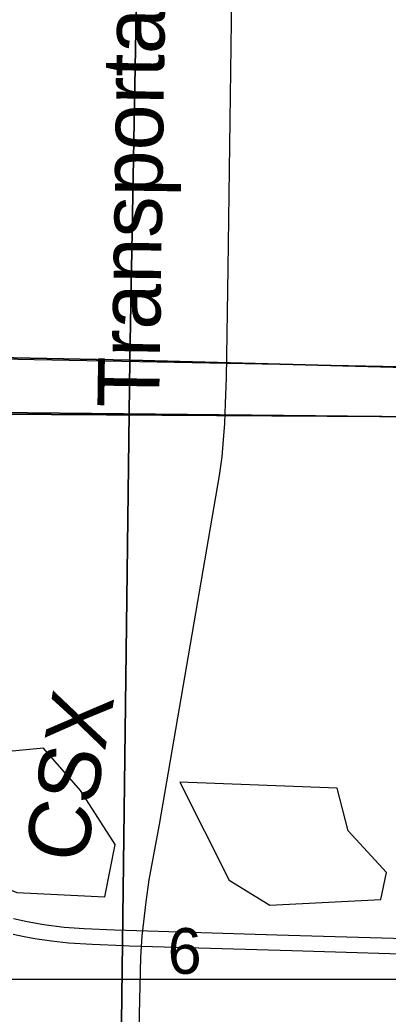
# Model space of a CAD drawing. Extents: x 0 to 68, y 0 to 52.9.
# Drawn here: x 44.214 to 44.57, y 34.705 to 35.667 of the extents above; entities that cross this region are included whole.
import ezdxf

# ---------------------------------------------------------------- set-up
doc = ezdxf.new("R2010")
doc.units = 0
for name, color, linetype in [('Default', 7, 'Continuous'), ('GM_X_Minor_Lake', 7, 'Continuous'), ('GM_X_State_Route', 7, 'Continuous'), ('GM_X_Township', 7, 'Continuous'), ('GM_X_Township_Road', 7, 'Continuous')]:
    doc.layers.add(name, color=color, linetype=linetype)

msp = doc.modelspace()

# ---------------------------------------------------------------- linework, layer by layer
at = {"layer": 'Default'}
msp.add_line((42.25806, 34.73908), (49.65006, 34.73908), dxfattribs=at)
for points in [[(43.11555, 36.67874), (44.34414, 36.66665), (44.32023, 35.33817), (43.69327, 35.3509), (43.1026, 35.34663), (43.11455, 36.64024)], [(44.34414, 36.66665), (45.68961, 36.62483), (45.66716, 35.30232), (44.32023, 35.33817)], [(43.90273, 36.34073), (44.95281, 36.32851), (44.93588, 35.27966), (44.90228, 35.2801), (43.8802, 35.29067)], [(43.1026, 35.34663), (43.69327, 35.3509), (44.32023, 35.33817), (44.30324, 34.00462), (43.08734, 34.03057), (43.1022, 35.31613)], [(44.32023, 35.33817), (45.66716, 35.30232), (45.64513, 33.97481), (44.30324, 34.00462)], [(43.8802, 35.29067), (44.90228, 35.2801), (44.84933, 34.26177), (43.86646, 34.27144)]]:
    msp.add_lwpolyline(points, close=True, dxfattribs=at)
msp.add_lwpolyline([(44.31563, 34.08514), (44.32283, 34.40479), (44.3263, 34.5659), (44.33075, 34.76036), (44.33208, 34.78081), (44.33589, 34.81407), (44.33886, 34.83523), (44.34894, 34.88875), (44.40681, 35.22658), (44.40934, 35.2448), (44.41073, 35.26095), (44.41212, 35.27682), (44.41282, 35.29617), (44.41352, 35.32123), (44.41519, 35.42702), (44.41987, 35.76131)], dxfattribs=at)
at = {"layer": 'GM_X_Minor_Lake'}
for points in [[(44.05625, 35.06822), (44.001, 35.0495), (44.0015, 34.97756), (44.09931, 34.86804), (44.21061, 34.82307), (44.29578, 34.81898)], [(44.05625, 35.06822), (44.001, 35.0495), (44.0015, 34.97756), (44.09931, 34.86804), (44.21061, 34.82307), (44.29578, 34.81898), (44.30592, 34.86951), (44.27227, 34.9217), (44.2365, 34.96266), (44.1319, 34.9529), (44.08508, 34.97428), (44.05625, 35.06822)], [(44.29578, 34.81898), (44.30592, 34.86951), (44.27227, 34.9217), (44.2365, 34.96266), (44.1319, 34.9529), (44.08508, 34.97428), (44.05625, 35.06822)], [(44.36842, 34.92995), (44.41612, 34.83501), (44.45568, 34.81089), (44.56305, 34.8162)], [(44.56305, 34.8162), (44.56853, 34.84227), (44.53155, 34.88284), (44.5207, 34.92395), (44.36842, 34.92995)], [(44.36842, 34.92995), (44.41612, 34.83501), (44.45568, 34.81089), (44.56305, 34.8162), (44.56853, 34.84227), (44.53155, 34.88284), (44.5207, 34.92395), (44.36842, 34.92995)]]:
    msp.add_lwpolyline(points, dxfattribs=at)
at = {"layer": 'GM_X_State_Route'}
for points in [[(44.20739, 34.79783), (44.22063, 34.79488), (44.23683, 34.7921), (44.25645, 34.78963), (44.27592, 34.78829), (44.30535, 34.78686), (44.31628, 34.78657), (44.46241, 34.78207), (44.54154, 34.77979), (44.67738, 34.7761)], [(44.20713, 34.7827), (44.21785, 34.7806), (44.22819, 34.7786), (44.24437, 34.77617), (44.26063, 34.77445), (44.2835, 34.77295), (44.31417, 34.77181)], [(44.31417, 34.77181), (44.31954, 34.77161), (44.47689, 34.76694), (44.62439, 34.76255), (44.73914, 34.7591), (44.95879, 34.75298), (45.14567, 34.74747), (45.20467, 34.74554), (45.28009, 34.74364), (45.57186, 34.73511), (45.72923, 34.73044), (45.83413, 34.72741)]]:
    msp.add_lwpolyline(points, dxfattribs=at)
at = {"layer": 'GM_X_Township'}
for points in [[(45.98487, 35.25468), (45.19609, 35.27373), (44.67116, 35.28291), (44.03026, 35.28678), (44.02565, 35.2866), (43.87984, 35.28929), (43.8838, 35.42872), (43.88554, 35.47765), (43.88559, 35.48361), (43.89433, 35.82141)], [(43.82555, 31.14308), (43.84116, 32.12518), (43.84157, 32.15139), (43.84801, 32.65058), (43.84836, 32.67758), (43.85768, 33.1798), (43.85826, 33.20494), (43.86306, 33.73951), (43.8693, 34.2426), (43.87279, 34.5425), (43.87416, 34.73517), (43.87728, 34.86863), (43.87373, 34.92293), (43.87405, 34.94019), (43.87961, 35.19356), (43.87966, 35.21517), (43.87984, 35.28929), (44.02565, 35.2866), (44.03026, 35.28678), (44.67116, 35.28291), (45.19609, 35.27373), (45.98487, 35.25468)]]:
    msp.add_lwpolyline(points, dxfattribs=at)
at = {"layer": 'GM_X_Township_Road'}
msp.add_lwpolyline([(43.10625, 35.34577), (43.11563, 35.34557), (43.11973, 35.34548), (43.24691, 35.3466), (43.39051, 35.34699), (43.50127, 35.34778), (43.63254, 35.34888), (43.74739, 35.34771), (43.99351, 35.34314), (44.06735, 35.34196), (44.22732, 35.33899), (44.46523, 35.33417), (44.78106, 35.32815), (44.99612, 35.32175)], dxfattribs=at)

# ---------------------------------------------------------------- texts
at = {"layer": 'Default'}
for s, height, rotation, p in [('Transportation,', 0.0598, 89.17029, (44.34844, 35.29203)), ('CSX', 0.0598, 80.02237, (44.27669, 34.84961)), ('6', 0.0442, 0.00001, (44.35673, 34.74441))]:
    msp.add_text(s, height=height, rotation=rotation, dxfattribs=at).set_placement(p)

doc.saveas('drawing.dxf')
